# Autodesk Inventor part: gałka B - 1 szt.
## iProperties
Created: 2024-06
Part Number: gałka B - 1 szt.
Document SubType Name: Modeling
Designer: Tomasz Łysek
Density: 1 g/cm^3
Author: Tomasz Łysek
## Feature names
1. Wyciągnięcie proste1 [Extrusion]
2. Wyciągnięcie proste2 [Extrusion]
3. Wyciągnięcie proste3 [Extrusion]
4. Wyciągnięcie proste4 [Extrusion]
5. Wyciągnięcie proste5 [Extrusion]
